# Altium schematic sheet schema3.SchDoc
size A3; ApprovedBy: CdB; CheckedBy: CdB; DrawnBy: RT; Engineer: CdB; Organization: Faber Electronics B.V.; Address1: Th. Dobbeweg 1,; Address2: 6883 GN Velp,; Address3: Netherlands; Address4: T: 026-38 46 800; DocumentNumber: 3; Revision: 2.1.4; SheetNumber: 3; SheetTotal: 6; Status: Final; PageSetup: Record=PageOptions|CenterHorizontal=True|CenterVertical=True|PrintScale=1.01|XCorrection=1.00|YCorrection=1.00|PrintKind=1|BorderSize=5000000|LeftOffset=0|BottomOffset=0|Orientation=2|PaperLength=1000|PaperWidth=1000|Scale=100|PaperSource=7|PrintQuality=600|MediaType=1|DitherType=10|PaperKind=A3 (297 x 420mm)|PrintScaleMode=1
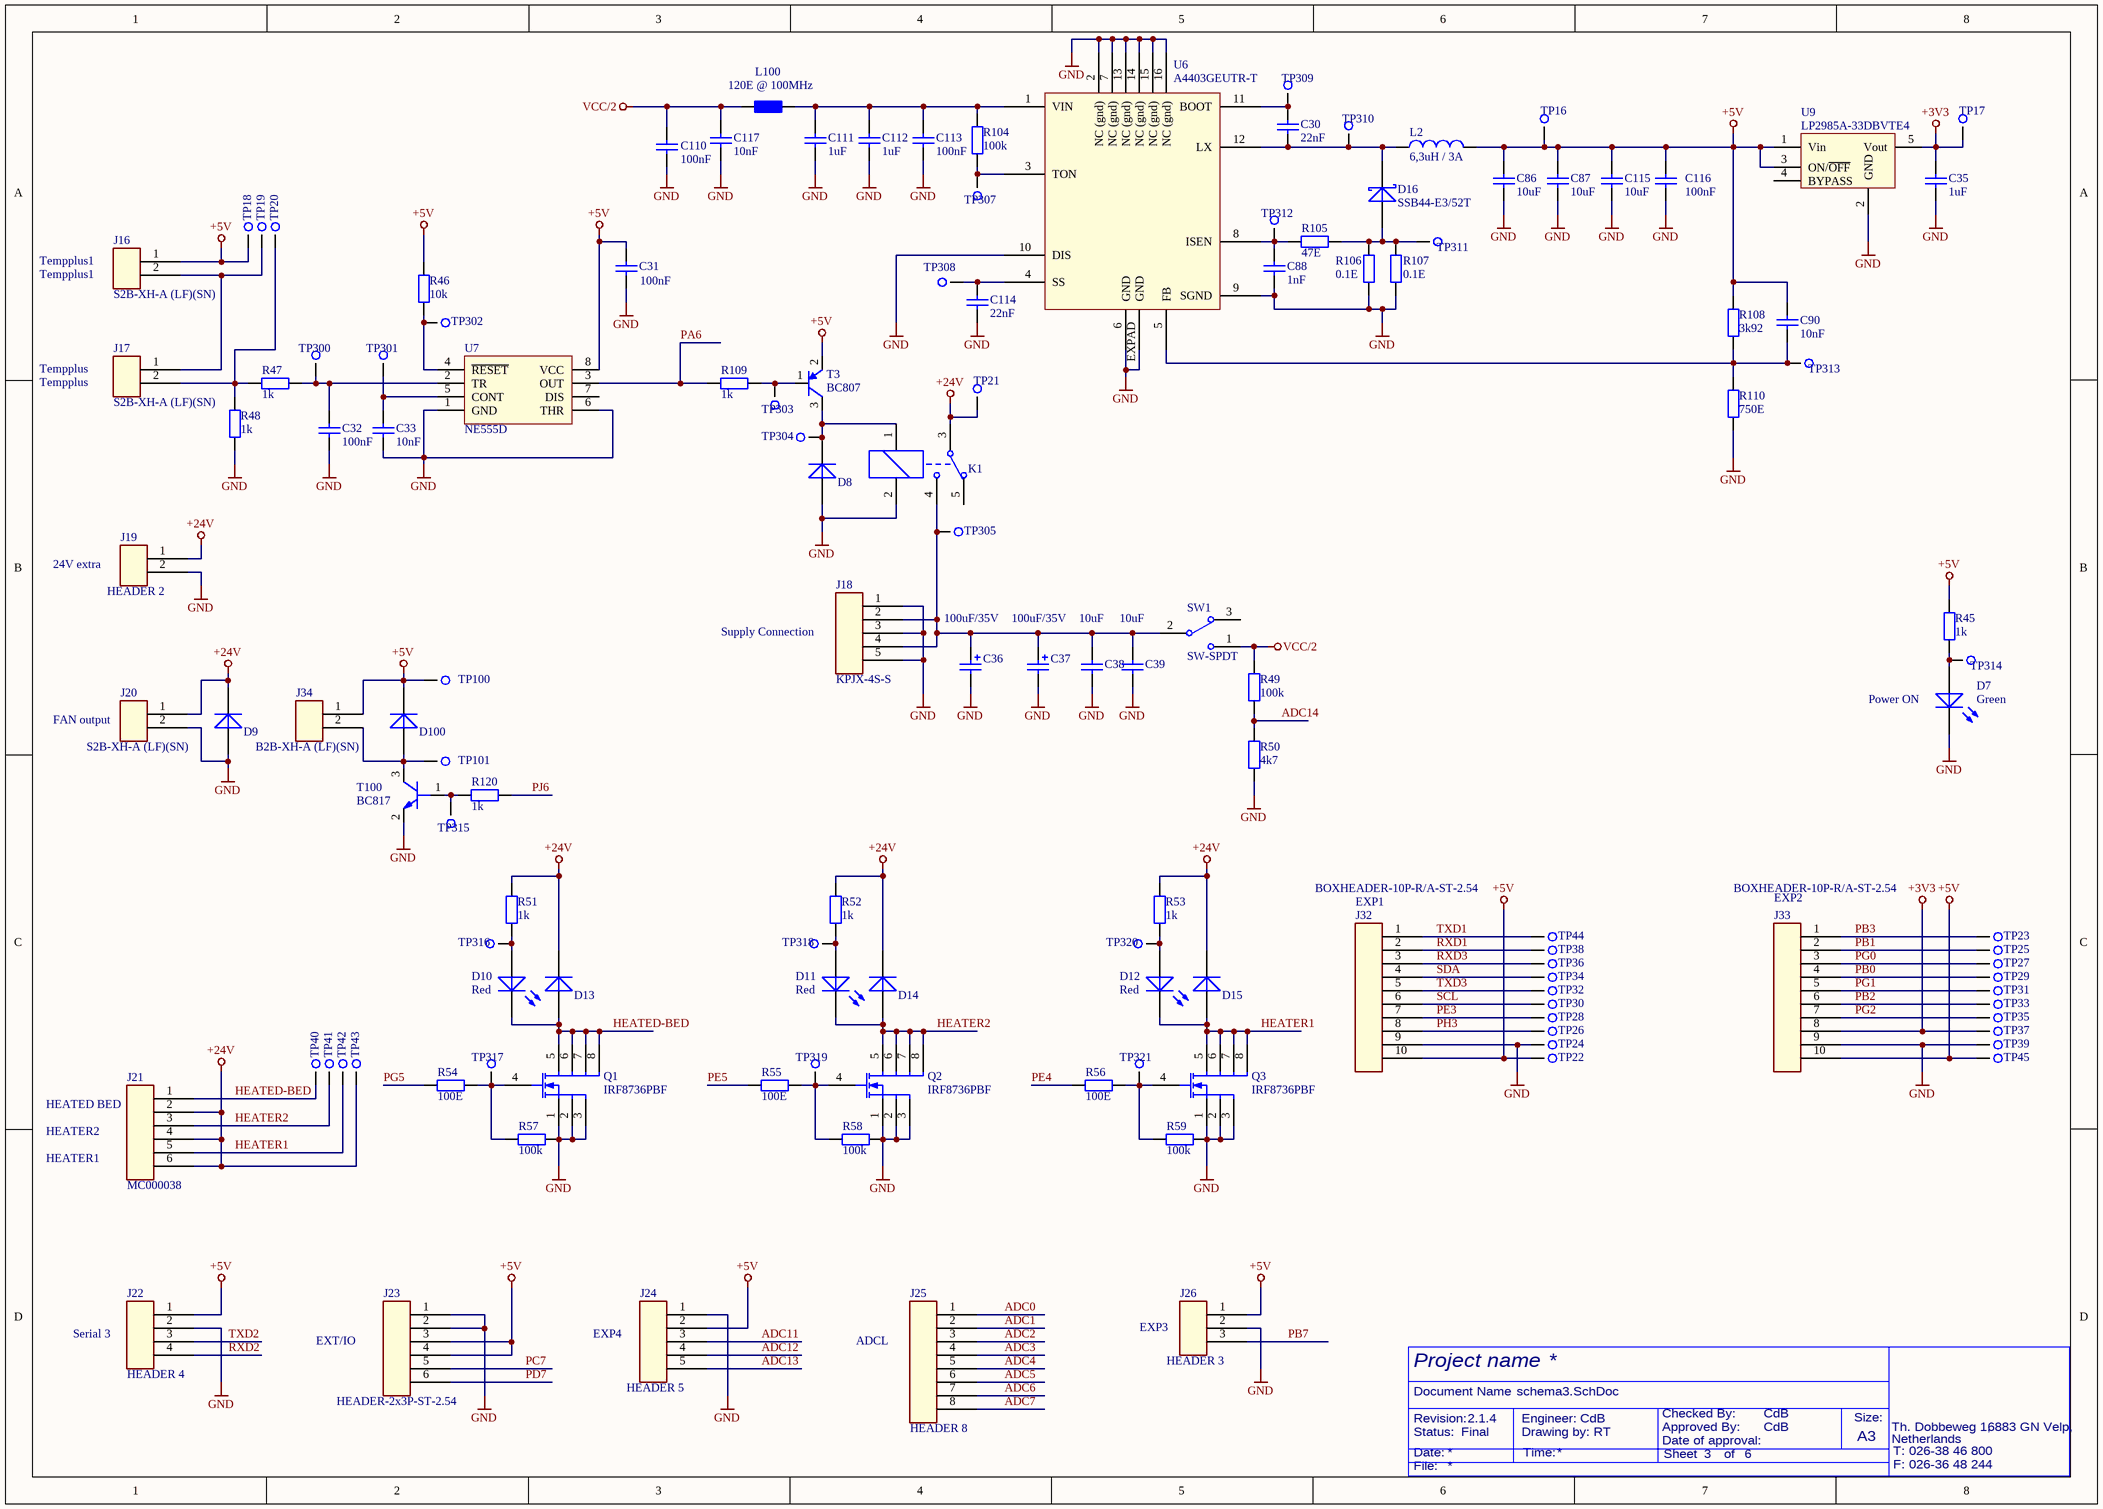
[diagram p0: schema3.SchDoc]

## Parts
C30  22nF  [C0603]
C31  100nF  [C0603]
C32  100nF  [C0603]
C33  10nF  [C0603]
C35  1uF  [C0603]
C36  100uF/35V  [ELCO Case D]
C37  100uF/35V  [ELCO Case D]
C38  10uF  [C1206]
C39  10uF  [C1206]
C86  10uF  [C0805]
C87  10uF  [C0805]
C88  1nF  [C0603]
C90  10nF  [C0603]
C110  100nF  [C0603]
C111  1uF  [C1206]
C112  1uF  [C1206]
C113  100nF  [C0603]
C114  22nF  [C0603]
C115  10uF  [C0805]
C116  100nF  [C0603]
C117  10nF  [C0603]
D7  Green  [LED0805-GREEN]
D8  S1G  [DO214AC (SMA)]  (value not drawn)
D9  S1G  [DO214AC (SMA)]  (value not drawn)
D10  Red  [LED0805-RED]
D11  Red  [LED0805-RED]
D12  Red  [LED0805-RED]
D13  S1G  [DO214AC (SMA)]  (value not drawn)
D14  S1G  [DO214AC (SMA)]  (value not drawn)
D15  S1G  [DO214AC (SMA)]  (value not drawn)
D16  SSB44-E3/52T  [DO214AA (SMB)]
D100  S1G  [DO214AC (SMA)]  (value not drawn)
J16  S2B-XH-A (LF)(SN)  [S2B-XH-A (LF)(SN)]
J17  S2B-XH-A (LF)(SN)  [S2B-XH-A (LF)(SN)]
J18  KPJX-4S-S  [KPJX-4S-S]
J19  HEADER 2  [HEADER-1x2P-ST-2.54]
J20  S2B-XH-A (LF)(SN)  [S2B-XH-A (LF)(SN)]
J21  MC000038  [MC000038]
J22  HEADER 4  [HEADER-1x4P-ST-2.54]
J23  HEADER-2x3P-ST-2.54  [HEADER-2x3P-ST-2.54]
J24  HEADER 5  [HEADER-1x5P-ST-2.54]
J25  HEADER 8  [HEADER-1x8P-ST-2.54]
J26  HEADER 3  [HEADER-1x3P-ST-2.54]
J32  BOXHEADER-10P-R/A-ST-2.54  [BOXHEADER-10P-R/A-ST-2.54]
J33  BOXHEADER-10P-R/A-ST-2.54  [BOXHEADER-10P-R/A-ST-2.54]
J34  B2B-XH-A (LF)(SN)  [B2B-XH-A (LF)(SN)]
K1  Relay-SPDT  [HRS4-S]  (value not drawn)
L2  6,3uH / 3A  [NRS6045]
L100  120E @ 100MHz  [R0603]
Q1  IRF8736PBF  [SOIC127P600X175-8N (SO8)]
Q2  IRF8736PBF  [SOIC127P600X175-8N (SO8)]
Q3  IRF8736PBF  [SOIC127P600X175-8N (SO8)]
R45  1k  [R0603]
R46  10k  [R0603]
R47  1k  [R0603]
R48  1k  [R0603]
R49  100k  [R0603]
R50  4k7  [R0603]
R51  1k  [R0603]
R52  1k  [R0603]
R53  1k  [R0603]
R54  100E  [R0603]
R55  100E  [R0603]
R56  100E  [R0603]
R57  100k  [R0603]
R58  100k  [R0603]
R59  100k  [R0603]
R104  100k  [R0603]
R105  47E  [R0603]
R106  0.1E  [R0805]
R107  0.1E  [R0805]
R108  3k92  [R0603]
R109  1k  [R0603]
R110  750E  [R0603]
R120  1k  [R0603]
SW1  SW-SPDT  [RS 734-6918]
T3  BC807  [SOT23]
T100  BC817  [SOT23]
TP16  Testpoint  [Testpoint]  (value not drawn)
TP17  Testpoint  [Testpoint]  (value not drawn)
TP18  Testpoint  [Testpoint]  (value not drawn)
TP19  Testpoint  [Testpoint]  (value not drawn)
TP20  Testpoint  [Testpoint]  (value not drawn)
TP21  Testpoint  [Testpoint]  (value not drawn)
TP22  Testpoint  [Testpoint]  (value not drawn)
TP23  Testpoint  [Testpoint]  (value not drawn)
TP24  Testpoint  [Testpoint]  (value not drawn)
TP25  Testpoint  [Testpoint]  (value not drawn)
TP26  Testpoint  [Testpoint]  (value not drawn)
TP27  Testpoint  [Testpoint]  (value not drawn)
TP28  Testpoint  [Testpoint]  (value not drawn)
TP29  Testpoint  [Testpoint]  (value not drawn)
TP30  Testpoint  [Testpoint]  (value not drawn)
TP31  Testpoint  [Testpoint]  (value not drawn)
TP32  Testpoint  [Testpoint]  (value not drawn)
TP33  Testpoint  [Testpoint]  (value not drawn)
TP34  Testpoint  [Testpoint]  (value not drawn)
TP35  Testpoint  [Testpoint]  (value not drawn)
TP36  Testpoint  [Testpoint]  (value not drawn)
TP37  Testpoint  [Testpoint]  (value not drawn)
TP38  Testpoint  [Testpoint]  (value not drawn)
TP39  Testpoint  [Testpoint]  (value not drawn)
TP40  Testpoint  [Testpoint]  (value not drawn)
TP41  Testpoint  [Testpoint]  (value not drawn)
TP42  Testpoint  [Testpoint]  (value not drawn)
TP43  Testpoint  [Testpoint]  (value not drawn)
TP44  Testpoint  [Testpoint]  (value not drawn)
TP45  Testpoint  [Testpoint]  (value not drawn)
TP100  Testpoint  [Testpoint]  (value not drawn)
TP101  Testpoint  [Testpoint]  (value not drawn)
TP300  Testpoint 1.6mm  [Testpoint 1.6mm]  (value not drawn)
TP301  Testpoint 1.6mm  [Testpoint 1.6mm]  (value not drawn)
TP302  Testpoint 1.6mm  [Testpoint 1.6mm]  (value not drawn)
TP303  Testpoint 1.6mm  [Testpoint 1.6mm]  (value not drawn)
TP304  Testpoint 1.6mm  [Testpoint 1.6mm]  (value not drawn)
TP305  Testpoint 1.6mm  [Testpoint 1.6mm]  (value not drawn)
TP307  Testpoint 1.6mm  [Testpoint 1.6mm]  (value not drawn)
TP308  Testpoint 1.6mm  [Testpoint 1.6mm]  (value not drawn)
TP309  Testpoint 1.6mm  [Testpoint 1.6mm]  (value not drawn)
TP310  Testpoint 1.6mm  [Testpoint 1.6mm]  (value not drawn)
TP311  Testpoint 1.6mm  [Testpoint 1.6mm]  (value not drawn)
TP312  Testpoint 1.6mm  [Testpoint 1.6mm]  (value not drawn)
TP313  Testpoint 1.6mm  [Testpoint 1.6mm]  (value not drawn)
TP314  Testpoint 1.6mm  [Testpoint 1.6mm]  (value not drawn)
TP315  Testpoint 1.6mm  [Testpoint 1.6mm]  (value not drawn)
TP316  Testpoint 1.6mm  [Testpoint 1.6mm]  (value not drawn)
TP317  Testpoint 1.6mm  [Testpoint 1.6mm]  (value not drawn)
TP318  Testpoint 1.6mm  [Testpoint 1.6mm]  (value not drawn)
TP319  Testpoint 1.6mm  [Testpoint 1.6mm]  (value not drawn)
TP320  Testpoint 1.6mm  [Testpoint 1.6mm]  (value not drawn)
TP321  Testpoint 1.6mm  [Testpoint 1.6mm]  (value not drawn)
U6  A4403GEUTR-T  [QFN65P400X400X80-16N-EX]
U7  NE555D  [SOIC127P600X175-8N (SO8)]
U9  LP2985A-33DBVTE4  [SOT95P280X145-5N (SOT23-5L)]

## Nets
+3V3: C35.2 J33.8 TP17.1 TP37.1 U9.5(Vout)
+5V: C31.2 C86.2 C87.2 C90.2 C115.2 C116.2 D100.2(K) J16.1 J22.1 J23.3 J23.4 J24.2 J26.1 J32.10 J33.10 J34.1 L2.2 R45.2 R46.2 R108.2 T3.2(E) TP16.1 TP18.1 TP22.1 TP45.1 TP100.1 U7.8(VCC) U9.1(Vin) U9.3(ON/~{OFF})
+24V: D9.2(K) D13.2(K) D14.2(K) D15.2(K) J19.1 J20.1 J21.2 J21.4 J21.6 K1.3 R51.2 R52.2 R53.2 TP21.1 TP43.1
GND: C31.1 C32.1 C33.1 C35.1 C36.2 C37.2 C38.1 C39.1 C86.1 C87.1 C88.1 C110.1 C111.1 C112.1 C113.1 C114.1 C115.1 C116.1 C117.1 D7.2(K) D8.1(A) D9.1(A) J18.1 J18.3 J18.5 J19.2 J20.2 J22.2 J23.1 J23.2 J24.1 J26.2 J32.9 J33.9 K1.2 Q1.1(S) Q1.2(S) Q1.3(S) Q2.1(S) Q2.2(S) Q2.3(S) Q3.1(S) Q3.2(S) Q3.3(S) R48.1 R50.1 R57.2 R58.2 R59.2 R106.1 R107.1 R110.1 T100.2(EMITTER) TP24.1 TP39.1 U6.2(NC_(gnd)) U6.6(GND) U6.7(NC_(gnd)) U6.9(SGND) U6.10(DIS) U6.13(NC_(gnd)) U6.14(NC_(gnd)) U6.15(NC_(gnd)) U6.16(NC_(gnd)) U6.EXPAD(GND) U7.1(GND) U7.6(THR) U9.2(GND)
VCC/2: C110.2 C117.2 L100.1 R49.2 SW1.1
ADC0: J25.1
ADC1: J25.2
ADC2: J25.3
ADC3: J25.4
ADC4: J25.5
ADC5: J25.6
ADC6: J25.7
ADC7: J25.8
ADC11: J24.3
ADC12: J24.4
ADC13: J24.5
ADC14: R49.1 R50.2
HEATED-BED: D10.2(K) D13.1(A) J21.1 Q1.5(D) Q1.6(D) Q1.7(D) Q1.8(D) TP40.1
HEATER1: D12.2(K) D15.1(A) J21.5 Q3.5(D) Q3.6(D) Q3.7(D) Q3.8(D) TP42.1
HEATER2: D11.2(K) D14.1(A) J21.3 Q2.5(D) Q2.6(D) Q2.7(D) Q2.8(D) TP41.1
PA6: R109.1 U7.3(OUT)
PB0: J33.4 TP29.1
PB1: J33.2 TP25.1
PB2: J33.6 TP33.1
PB3: J33.1 TP23.1
PB7: J26.3
PC7: J23.5
PD7: J23.6
PE3: J32.7 TP28.1
PE4: R56.1
PE5: R55.1
PG0: J33.3 TP27.1
PG1: J33.5 TP31.1
PG2: J33.7 TP35.1
PG5: R54.1
PH3: J32.8 TP26.1
PJ6: R120.1
RXD1: J32.2 TP38.1
RXD2: J22.4
RXD3: J32.3 TP36.1
SCL: J32.6 TP30.1
SDA: J32.4 TP34.1
TXD1: J32.1 TP44.1
TXD2: J22.3
TXD3: J32.5 TP32.1
NetC30_1: C30.1 D16.2(K) L2.1 TP310.1 U6.12(LX)
NetC30_2: C30.2 TP309.1 U6.11(BOOT)
NetC32_2: C32.2 R47.2 TP300.1 U7.2(TR)
NetC33_2: C33.2 TP301.1 U7.5(CONT)
NetC36_1: C36.1 C37.1 C38.2 C39.2 J18.2 J18.4 K1.4 SW1.2 TP305.1
NetC88_2: C88.2 R105.1 TP312.1 U6.8(ISEN)
NetC90_1: C90.1 R108.1 R110.2 TP313.1 U6.5(FB)
NetC111_2: C111.2 C112.2 C113.2 L100.2 R104.2 U6.1(VIN)
NetC114_2: C114.2 TP308.1 U6.4(SS)
NetD7_1: D7.1(A) R45.1 TP314.1
NetD8_2: D8.2(K) K1.1 T3.3(C) TP304.1
NetD10_1: D10.1(A) R51.1 TP316.1
NetD11_1: D11.1(A) R52.1 TP318.1
NetD12_1: D12.1(A) R53.1 TP320.1
NetD16_1: D16.1(A) R105.2 R106.2 R107.2 TP311.1
NetD100_1: D100.1(A) J34.2 T100.3(COLLECTOR) TP101.1
NetJ16_2: J16.2 J17.1 TP19.1
NetJ17_2: J17.2 R47.1 R48.2 TP20.1
NetQ1_4: Q1.4(G) R54.2 R57.1 TP317.1
NetQ2_4: Q2.4(G) R55.2 R58.1 TP319.1
NetQ3_4: Q3.4(G) R56.2 R59.1 TP321.1
NetR46_1: R46.1 TP302.1 U7.4(~{RESET})
NetR104_1: R104.1 TP307.1 U6.3(TON)
NetR109_2: R109.2 T3.1(B) TP303.1
NetR120_2: R120.2 T100.1(BASE) TP315.1

Not connected (* = marked no-connect by the designer): K1 5; SW1 3; U7 7(DIS); U9 4(BYPASS)

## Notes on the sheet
- (near J16) Tempplus1
- (near J17) Tempplus
- (near J19) 24V extra
- (near J18) Supply Connection
- (near J20) FAN output
- (near D7) Power ON
- (near J32) EXP1
- (near J33) EXP2
- (near J21) HEATED BED
- HEATER1
- HEATER2
- (near J22) Serial 3
- EXT/IO
- (near J24) EXP4
- ADCL
- (near J26) EXP3

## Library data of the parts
C30 C114 = Library_CAP-0011: RO X7R 22nF 10% 0603 50V CC0603KRX7R9BB223; Faber ItemCode: 36795200
C31 C32 C110 C113 C116 = Library_CAP-0002: RO X7R 100nF 10% 50V 0603; Faber ItemCode: 45068500
C33 C90 C117 = Library_CAP-0007: RO X7R 10nF 10% 50V 0603; Faber ItemCode: 36270400
C35 = Library_CAP-0006: RO X5R 1uF 10% 10V 0603; Faber ItemCode: 36310600
C36 C37 = Library_CAP-0004: RO ELCO 100uF 20% 35V CASE-D EEEFP PAN; Faber ItemCode: 36865800
C38 C39 = Library_CAP-0005: RO X5R 10UF 10% 35V 1206; Faber ItemCode: 35436800
C86 C87 C115 = Library_CAP-0012: 6R3R15X106KV4E - MLCC, 0805, X5R, 6.3V, 10UF; Mfg: JOHANSON DIELECTRICS
C88 = Library_CAP-0013: RO C0G 1nF 5% 50V 0603; Faber ItemCode: 35288300
C111 C112 = Capacitor_1_1: X7R 1uF 10% 50V 1206 GRM31; ID: Library_CAP-0005; Faber ItemCode: 35387100
D7 = Library_LED-0002: RO LED GROEN HSMG-C170 0805 AVAGO; Faber ItemCode: 35162200
D8 D9 D13-D15 D100 = Library_DIO-0001: RO DIODE S1G DO-214AC; Faber ItemCode: 32284000; Info: Fast Rectifiers 1A 400V
D10-D12 = Library_LED-0001: RO LED ROOD HSMH-C170 0805 AVAGO; Faber ItemCode: 35162100
D16 = Library_DIO-0003: RO DIODE SSB44-E3/52T SMB VISHAY; Info: High-Current Density Surface Mount Schottky Rectifier; Faber ItemCode: 36925500
J16 J17 J20 = Library_CON-0004: RO CONN PR 2p HKS S2B-XH-A (LF)(SN) JST; Mfg: JST (JAPAN SOLDERLESS TERMINALS); Faber ItemCode: 36926700
J18 = Library_CON-0009: RO CONN PR KPJX-4S-S KYCON; Info: Shielded version; Faber ItemCode: 36925000
J19 = Library_CON-0013: HEADER-1x2P-ST-2.54
J21 = Library_CON-0008: RO CONN PR 6p MC000038 MULTICOMP; Faber ItemCode: 36925200
J22 = Library_CON-0014: HEADER-1x4P-ST-2.54
J23 = Library_CON-0003: RO CONN PR HDR 2X3P H4B-06DS-0000 INT; Faber ItemCode: 35149900
J24 = Library_CON-0015: HEADER-1x5P-ST-2.54
J25 = Library_CON-0016: HEADER-1x8P-ST-2.54
J26 = Library_CON-0017: HEADER-1x3P-ST-2.54
J32 J33 = Library_CON-0019: RO CONN PR HDR BOX 10p HKS 61201021721 WUERTH; Faber ItemCode: 36925800
J34 = HEADER 2_3: CONN PR 2p B2B-XH-A JST; ID: Library_CON-0004; Mfg: JST (JAPAN SOLDERLESS TERMINALS); Faber ItemCode: 36863500
K1 = Library_REL-0001: RO REL 5V HRS4-S DC5V MULTICOMP; Faber ItemCode: 36924900
L2 = Library_COIL-0002: RO SPOEL 6,3uH 20% NRS6045T 6R3MMGK TAIYO YUDEN; Faber ItemCode: 36925300
L100 = Ferriet Bead 120E: FERRIET BLM18PG121SN1D 0603 MURATA; Info: Resistor
Q1-Q3 = LIBRARY_FET-0002: IRF8736PBF - MOSFET, N SO-8; Mfg: INTERNATIONAL RECTIFIER; Info: HEXFET Power MOSFET; Faber ItemCode: 36926000
R45 R47 R48 R51-R53 R109 R120 = Library_RES-0004: RO RES 1k0 1% 0,1W  0603; Faber ItemCode: 34637900
R46 = Library_RES-0001: RO RES 10k0 1% 0,063W  0603; Faber ItemCode: 36084500
R49 R57-R59 R104 = Library_RES-0005: RO RES 100k0 1% 0,063W  0603; Faber ItemCode: 36257800
R50 = Library_RES-0002: RO RES 4k70 1% 0,063W  0603; Faber ItemCode: 36257400
R54-R56 = Library_RES-0006: RO RES 100E 1% 0,063W  0603; Faber ItemCode: 32338800
R105 = Library_RES-0017: RO RES 47E 1% 0,063W 0603; Faber ItemCode: 35030300
R106 R107 = Library_RES-0016: RES 0E10 1% 0,125W 0805; Faber ItemCode: 35343500
R108 = Library_RES-0014: RO RES 3k92 1% 0.063W 0603; Faber ItemCode: 36767900
R110 = Library_RES-0015: RO RES 750E 1% 0,063W 0603; Faber ItemCode: 35154200
SW1 = Library_SWI-0001: Rocker switch,SPDT,on-none-on,RA,snap-in; Mfg: RS Components; Mfg code: 4MS1R202BM6NQNS; Faber ItemCode: 36925400
T3 = Library_TRA-0002: RO TRANS BC807-40  SOT-23; Faber ItemCode: 30827800; Info: 45 V, 500 mA PNP general-purpose transistors
T100 = Library_TRA-0001: RO TRANS BC817-25  SOT-23; Faber ItemCode: 30828000; Info: 45 V, 500 mA NPN general-purpose transistors
TP16-TP45 TP100 TP101 = Library_MISC-0001: Info: Testpoint, 2mm, round
TP300-TP305 TP307-TP321 = Testpoint 1.6mm: ID: Library_MISC-0001
U6 = Library_ICS-0010: RO IC A4403GEUTR-T QFN-16 ALLEGRO; Info: Valley Current Mode Control Buck Converter; Faber ItemCode: 36924500
U7 = Library_ICS-0009: RO IC NE555D SO-08 TI; Faber ItemCode: 35318300; Mfg: Texas Instruments; Mfg code: SE555DRG4; Info: PRECISION TIMER
U9 = Library_ICS-0008: RO STABI LP2985A-33DBVTE4 SOT-23-5 TI; Mfg: Texas Instruments; Info: 150-mA LOW-NOISE LOW-DROPOUT REGULATOR WITH SHUTDOWN; Faber ItemCode: 36925100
